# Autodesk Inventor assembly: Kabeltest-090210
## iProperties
Category: BG
Manager: Dr.-Ing. Roland Schröder
Company: Das Entwicklungsbüro
Created: 2009-02
Part Number: Kabeltest-090210
Material: ---
Document SubType Name: Assembly
Designer: R.Schröder
Mass: 2.55917 g
Surface Area: 35.8749 cm^2
Volume: 2.20598 cm^3
Density: 1.1601 g/cm^3
Author: R.Schröder
